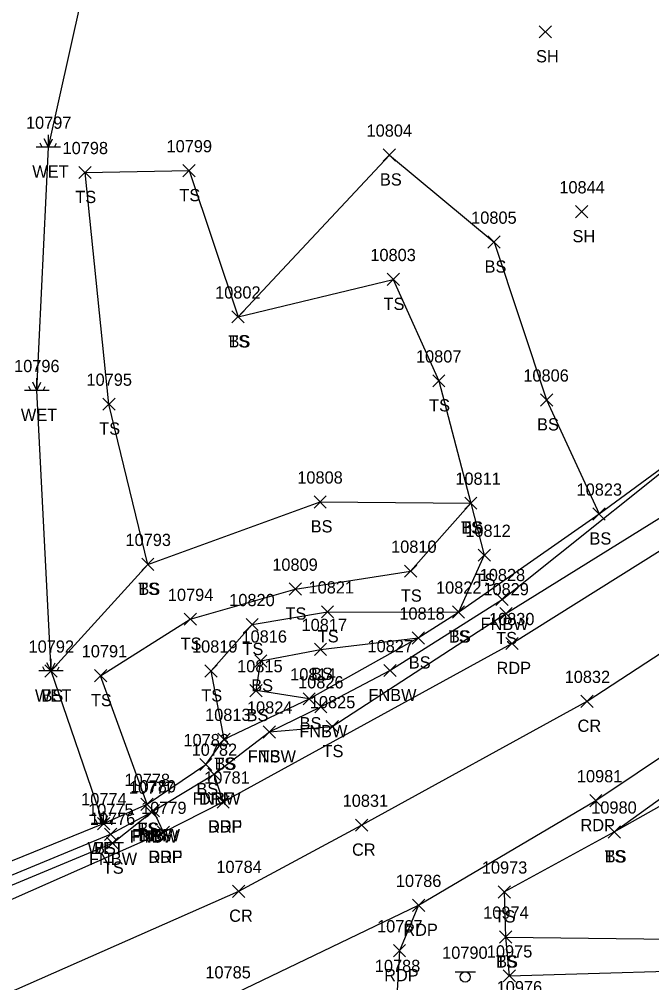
# Model space of a CAD drawing. Extents: x 1475671 to 1477951, y 592661 to 593821.
# Drawn here: x 1476484.8 to 1476588.2, y 593075.6 to 593233.2 of the extents above; entities that cross this region are included whole.
import ezdxf

# ---------------------------------------------------------------- set-up
doc = ezdxf.new("R2010")
doc.units = 0
for name, color, linetype in [('L_A', 7, 'Continuous'), ('L_I', 7, 'Continuous'), ('L_TIC', 7, 'Continuous'), ('LELB', 7, 'Continuous'), ('LFNC', 7, 'Continuous'), ('LWET', 7, 'Continuous'), ('P_A', 7, 'Continuous'), ('P_I', 7, 'Continuous'), ('P_TIC', 7, 'Continuous'), ('PET', 7, 'Continuous'), ('PRC', 7, 'Continuous'), ('R_A', 7, 'Continuous'), ('R_I', 7, 'Continuous'), ('R_TIC', 7, 'Continuous'), ('RDF', 7, 'Continuous'), ('S_I', 7, 'Continuous'), ('SSGN', 7, 'Continuous')]:
    doc.layers.add(name, color=color, linetype=linetype)

msp = doc.modelspace()

# ---------------------------------------------------------------- linework, layer by layer
at = {"layer": 'L_TIC'}
for points in [[(1476569.83, 593230.17), (1476571.83, 593232.17)], [(1476571.83, 593230.17), (1476569.83, 593232.17)], [(1476544.34, 593210.01), (1476546.34, 593212.01)], [(1476546.34, 593210.01), (1476544.34, 593212.01)], [(1476494.55, 593207.15), (1476496.55, 593209.15)], [(1476496.55, 593207.15), (1476494.55, 593209.15)], [(1476511.57, 593207.45), (1476513.57, 593209.45)], [(1476513.57, 593207.45), (1476511.57, 593209.45)], [(1476575.79, 593200.73), (1476577.79, 593202.73)], [(1476577.79, 593200.73), (1476575.79, 593202.73)], [(1476561.46, 593195.76), (1476563.46, 593197.76)], [(1476563.46, 593195.76), (1476561.46, 593197.76)], [(1476544.97, 593189.65), (1476546.97, 593191.65)], [(1476546.97, 593189.65), (1476544.97, 593191.65)], [(1476519.58, 593183.52), (1476521.58, 593185.52)], [(1476521.58, 593183.52), (1476519.58, 593185.52)], [(1476519.58, 593183.52), (1476521.58, 593185.52)], [(1476521.58, 593183.52), (1476519.58, 593185.52)], [(1476552.42, 593173.05), (1476554.42, 593175.05)], [(1476554.42, 593173.05), (1476552.42, 593175.05)], [(1476498.46, 593169.24), (1476500.46, 593171.24)], [(1476500.46, 593169.24), (1476498.46, 593171.24)], [(1476570.05, 593169.93), (1476572.05, 593171.93)], [(1476572.05, 593169.93), (1476570.05, 593171.93)], [(1476533.02, 593153.24), (1476535.02, 593155.24)], [(1476535.02, 593153.24), (1476533.02, 593155.24)], [(1476557.65, 593153.04), (1476559.65, 593155.04)], [(1476559.65, 593153.04), (1476557.65, 593155.04)], [(1476557.65, 593153.04), (1476559.65, 593155.04)], [(1476559.65, 593153.04), (1476557.65, 593155.04)], [(1476557.65, 593153.04), (1476559.65, 593155.04)], [(1476559.65, 593153.04), (1476557.65, 593155.04)], [(1476578.62, 593151.26), (1476580.62, 593153.26)], [(1476580.62, 593151.26), (1476578.62, 593153.26)], [(1476578.62, 593151.26), (1476580.62, 593153.26)], [(1476580.62, 593151.26), (1476578.62, 593153.26)], [(1476559.85, 593144.52), (1476561.85, 593146.52)], [(1476561.85, 593144.52), (1476559.85, 593146.52)], [(1476504.83, 593143.02), (1476506.83, 593145.02)], [(1476506.83, 593143.02), (1476504.83, 593145.02)], [(1476504.83, 593143.02), (1476506.83, 593145.02)], [(1476506.83, 593143.02), (1476504.83, 593145.02)], [(1476547.8, 593141.91), (1476549.8, 593143.91)], [(1476549.8, 593141.91), (1476547.8, 593143.91)], [(1476528.94, 593138.97), (1476530.94, 593140.97)], [(1476530.94, 593138.97), (1476528.94, 593140.97)], [(1476562.76, 593137.28), (1476564.76, 593139.28)], [(1476564.76, 593137.28), (1476562.76, 593139.28)], [(1476511.77, 593134.04), (1476513.77, 593136.04)], [(1476513.77, 593134.04), (1476511.77, 593136.04)], [(1476534.22, 593135.25), (1476536.22, 593137.25)], [(1476536.22, 593135.25), (1476534.22, 593137.25)], [(1476555.63, 593135.22), (1476557.63, 593137.22)], [(1476557.63, 593135.22), (1476555.63, 593137.22)], [(1476555.63, 593135.22), (1476557.63, 593137.22)], [(1476557.63, 593135.22), (1476555.63, 593137.22)], [(1476555.63, 593135.22), (1476557.63, 593137.22)], [(1476557.63, 593135.22), (1476555.63, 593137.22)], [(1476563.39, 593134.96), (1476565.39, 593136.96)], [(1476565.39, 593134.96), (1476563.39, 593136.96)], [(1476521.89, 593133.18), (1476523.89, 593135.18)], [(1476523.89, 593133.18), (1476521.89, 593135.18)], [(1476549.06, 593130.97), (1476551.06, 593132.97)], [(1476551.06, 593130.97), (1476549.06, 593132.97)], [(1476549.06, 593130.97), (1476551.06, 593132.97)], [(1476551.06, 593130.97), (1476549.06, 593132.97)], [(1476533.07, 593129.11), (1476535.07, 593131.11)], [(1476535.07, 593129.11), (1476533.07, 593131.11)], [(1476523.3, 593127.22), (1476525.3, 593129.22)], [(1476525.3, 593127.22), (1476523.3, 593129.22)], [(1476488.99, 593125.57), (1476490.99, 593127.57)], [(1476490.99, 593125.57), (1476488.99, 593127.57)], [(1476497.11, 593124.8), (1476499.11, 593126.8)], [(1476499.11, 593124.8), (1476497.11, 593126.8)], [(1476515.16, 593125.58), (1476517.16, 593127.58)], [(1476517.16, 593125.58), (1476515.16, 593127.58)], [(1476544.43, 593125.64), (1476546.43, 593127.64)], [(1476546.43, 593125.64), (1476544.43, 593127.64)], [(1476522.53, 593122.35), (1476524.53, 593124.35)], [(1476524.53, 593122.35), (1476522.53, 593124.35)], [(1476531.21, 593121.02), (1476533.21, 593123.02)], [(1476533.21, 593121.02), (1476531.21, 593123.02)], [(1476531.21, 593121.02), (1476533.21, 593123.02)], [(1476533.21, 593121.02), (1476531.21, 593123.02)], [(1476533.13, 593119.72), (1476535.13, 593121.72)], [(1476535.13, 593119.72), (1476533.13, 593121.72)], [(1476524.71, 593115.6), (1476526.71, 593117.6)], [(1476526.71, 593115.6), (1476524.71, 593117.6)], [(1476524.71, 593115.6), (1476526.71, 593117.6)], [(1476526.71, 593115.6), (1476524.71, 593117.6)], [(1476534.99, 593116.47), (1476536.99, 593118.47)], [(1476536.99, 593116.47), (1476534.99, 593118.47)], [(1476517.29, 593114.4), (1476519.29, 593116.4)], [(1476519.29, 593114.4), (1476517.29, 593116.4)], [(1476517.29, 593114.4), (1476519.29, 593116.4)], [(1476519.29, 593114.4), (1476517.29, 593116.4)], [(1476514.32, 593110.26), (1476516.32, 593112.26)], [(1476516.32, 593110.26), (1476514.32, 593112.26)], [(1476515.66, 593108.69), (1476517.66, 593110.69)], [(1476517.66, 593108.69), (1476515.66, 593110.69)], [(1476504.69, 593103.75), (1476506.69, 593105.75)], [(1476506.69, 593103.75), (1476504.69, 593105.75)], [(1476504.69, 593103.75), (1476506.69, 593105.75)], [(1476506.69, 593103.75), (1476504.69, 593105.75)], [(1476505.4, 593102.47), (1476507.4, 593104.47)], [(1476507.4, 593102.47), (1476505.4, 593104.47)], [(1476505.4, 593102.47), (1476507.4, 593104.47)], [(1476507.4, 593102.47), (1476505.4, 593104.47)], [(1476505.74, 593102.7), (1476507.74, 593104.7)], [(1476507.74, 593102.7), (1476505.74, 593104.7)], [(1476497.59, 593100.6), (1476499.59, 593102.6)], [(1476499.59, 593100.6), (1476497.59, 593102.6)], [(1476581.11, 593099.23), (1476583.11, 593101.23)], [(1476583.11, 593099.23), (1476581.11, 593101.23)], [(1476581.11, 593099.23), (1476583.11, 593101.23)], [(1476583.11, 593099.23), (1476581.11, 593101.23)], [(1476498.73, 593098.84), (1476500.73, 593100.84)], [(1476500.73, 593098.84), (1476498.73, 593100.84)], [(1476499.05, 593097.39), (1476501.05, 593099.39)], [(1476501.05, 593097.39), (1476499.05, 593099.39)], [(1476563.12, 593089.41), (1476565.12, 593091.41)], [(1476565.12, 593089.41), (1476563.12, 593091.41)], [(1476563.12, 593089.41), (1476565.12, 593091.41)], [(1476565.12, 593089.41), (1476563.12, 593091.41)], [(1476563.35, 593082.03), (1476565.35, 593084.03)], [(1476565.35, 593082.03), (1476563.35, 593084.03)], [(1476563.35, 593082.03), (1476565.35, 593084.03)], [(1476565.35, 593082.03), (1476563.35, 593084.03)], [(1476563.94, 593075.68), (1476565.94, 593077.68)], [(1476565.94, 593075.68), (1476563.94, 593077.68)]]:
    msp.add_lwpolyline(points, dxfattribs=at)
at = {"layer": 'LELB'}
for points in [[(1476525.71, 593116.6), (1476535.99, 593117.47), (1476564.39, 593135.96), (1476604.97, 593161.16), (1476624.83, 593173.86), (1476638.09, 593183.34), (1476660.79, 593199.46), (1476676.81, 593212.32), (1476707.13, 593238.69), (1476723.81, 593252.6), (1476754.14, 593278.44), (1476785.31, 593303.01), (1476812.8, 593326.19), (1476842.99, 593352.59), (1476863.07, 593369.43), (1476886.56, 593389.77), (1476893.66, 593396.85), (1476901.2, 593401.68), (1476921.17, 593422.2)], [(1476564.12, 593090.41), (1476582.11, 593100.23), (1476611.48, 593121.39), (1476618.84, 593125.52), (1476623.35, 593128.86), (1476625.72, 593132.79), (1476629.36, 593135.67), (1476655.41, 593152.72), (1476679.21, 593171.49), (1476707, 593193.97), (1476724.55, 593208.7), (1476750.98, 593231.69), (1476770.54, 593248.26), (1476798.66, 593272.17), (1476825.82, 593296.2), (1476846.6, 593313.13), (1476851.35, 593312.9), (1476856.13, 593310.72)], [(1476520.58, 593184.52), (1476545.34, 593211.01), (1476562.46, 593196.76), (1476571.05, 593170.93), (1476579.62, 593152.26)], [(1476505.83, 593144.02), (1476499.46, 593170.24), (1476495.55, 593208.15), (1476512.57, 593208.45), (1476520.58, 593184.52), (1476545.97, 593190.65), (1476553.42, 593174.05), (1476558.65, 593154.04)], [(1476498.59, 593101.6), (1476505.69, 593104.75), (1476515.32, 593111.26), (1476518.29, 593115.4), (1476532.21, 593122.02), (1476550.06, 593131.97), (1476556.63, 593136.22), (1476579.62, 593152.26), (1476600.34, 593167.51), (1476602.47, 593173.82), (1476609.32, 593177.24)], [(1476489.99, 593126.57), (1476505.83, 593144.02), (1476534.02, 593154.24), (1476558.65, 593154.04)], [(1476505.69, 593104.75), (1476498.11, 593125.8), (1476512.77, 593135.04), (1476529.94, 593139.97), (1476548.8, 593142.91), (1476558.65, 593154.04), (1476560.85, 593145.52), (1476556.63, 593136.22)], [(1476518.29, 593115.4), (1476516.16, 593126.58), (1476522.89, 593134.18), (1476535.22, 593136.25), (1476556.63, 593136.22)], [(1476532.21, 593122.02), (1476523.53, 593123.35), (1476524.3, 593128.22), (1476534.07, 593130.11), (1476550.06, 593131.97)], [(1476582.11, 593100.23), (1476614.41, 593118.48), (1476620.24, 593123.64)], [(1476399.83, 593064.01), (1476416.3, 593067.79), (1476459.07, 593081.3), (1476500.05, 593098.39), (1476506.4, 593103.47)], [(1476564.12, 593090.41), (1476564.35, 593083.03), (1476564.94, 593076.68), (1476605.53, 593077.89), (1476635.38, 593080.86), (1476648.64, 593080.65), (1476656.7, 593082.36), (1476660.67, 593090.95), (1476671.66, 593086.36), (1476683.75, 593088.18), (1476716.34, 593096.61), (1476747.99, 593101.23)], [(1476564.35, 593083.03), (1476605.05, 593082.49), (1476634.15, 593084.51)]]:
    msp.add_lwpolyline(points, dxfattribs=at)
at = {"layer": 'LFNC'}
msp.add_lwpolyline([(1476458.99, 593083.01), (1476499.73, 593099.84), (1476506.4, 593103.47), (1476506.74, 593103.7), (1476516.66, 593109.69), (1476525.71, 593116.6), (1476534.13, 593120.72), (1476545.43, 593126.64), (1476563.76, 593138.28), (1476600.34, 593167.51), (1476610.45, 593174.4), (1476612.65, 593176.23), (1476618.95, 593180.66), (1476640, 593195.61), (1476653.4, 593207.77), (1476664.49, 593217.17), (1476691.69, 593239.4), (1476702.63, 593247.23), (1476709.5, 593251.9), (1476716.55, 593257.09), (1476733.12, 593270.47), (1476759.81, 593293.37)], dxfattribs=at)
at = {"layer": 'LWET'}
for p, q in [((1476489.56, 593212.3), (1476488.89, 593213.63)), ((1476489.56, 593212.3), (1476489.56, 593214.3)), ((1476489.56, 593212.3), (1476490.22, 593213.63)), ((1476491.56, 593212.3), (1476487.56, 593212.3)), ((1476488.56, 593212.3), (1476488.22, 593212.97)), ((1476490.56, 593212.3), (1476490.89, 593212.97)), ((1476487.68, 593172.48), (1476487.01, 593173.81)), ((1476487.68, 593172.48), (1476487.68, 593174.48)), ((1476487.68, 593172.48), (1476488.34, 593173.81)), ((1476489.68, 593172.48), (1476485.68, 593172.48)), ((1476486.68, 593172.48), (1476486.34, 593173.15)), ((1476488.68, 593172.48), (1476489.01, 593173.15)), ((1476489.99, 593126.57), (1476489.99, 593128.57)), ((1476491.99, 593126.57), (1476487.99, 593126.57)), ((1476488.99, 593126.57), (1476488.66, 593127.24)), ((1476489.99, 593126.57), (1476489.33, 593127.9)), ((1476489.99, 593126.57), (1476490.66, 593127.9)), ((1476490.99, 593126.57), (1476491.33, 593127.24)), ((1476498.59, 593101.6), (1476497.93, 593102.93)), ((1476498.59, 593101.6), (1476498.59, 593103.6)), ((1476498.59, 593101.6), (1476499.26, 593102.93)), ((1476500.59, 593101.6), (1476496.59, 593101.6)), ((1476497.59, 593101.6), (1476497.26, 593102.26)), ((1476499.59, 593101.6), (1476499.93, 593102.26))]:
    msp.add_line(p, q, dxfattribs=at)
msp.add_lwpolyline([(1476438.09, 593181.37), (1476442.92, 593155.18), (1476449.77, 593118.79), (1476457.34, 593084.84), (1476498.59, 593101.6), (1476489.99, 593126.57), (1476487.68, 593172.48), (1476489.56, 593212.3), (1476496.66, 593244.14)], dxfattribs=at)
at = {"layer": 'P_TIC'}
for points in [[(1476564.38, 593130.07), (1476566.38, 593132.07)], [(1476566.38, 593130.07), (1476564.38, 593132.07)], [(1476576.67, 593120.61), (1476578.67, 593122.61)], [(1476578.67, 593120.61), (1476576.67, 593122.61)], [(1476517.15, 593104.13), (1476519.15, 593106.13)], [(1476519.15, 593104.13), (1476517.15, 593106.13)], [(1476578.1, 593104.35), (1476580.1, 593106.35)], [(1476580.1, 593104.35), (1476578.1, 593106.35)], [(1476539.79, 593100.34), (1476541.79, 593102.34)], [(1476541.79, 593100.34), (1476539.79, 593102.34)], [(1476507.39, 593099.17), (1476509.39, 593101.17)], [(1476509.39, 593099.17), (1476507.39, 593101.17)], [(1476519.7, 593089.52), (1476521.7, 593091.52)], [(1476521.7, 593089.52), (1476519.7, 593091.52)], [(1476549.12, 593087.22), (1476551.12, 593089.22)], [(1476551.12, 593087.22), (1476549.12, 593089.22)], [(1476549.12, 593087.22), (1476551.12, 593089.22)], [(1476551.12, 593087.22), (1476549.12, 593089.22)], [(1476545.99, 593079.79), (1476547.99, 593081.79)], [(1476547.99, 593079.79), (1476545.99, 593081.79)]]:
    msp.add_lwpolyline(points, dxfattribs=at)
at = {"layer": 'PET'}
for points in [[(1476459.25, 593078.48), (1476508.39, 593100.17), (1476518.15, 593105.13), (1476565.38, 593131.07), (1476607.43, 593157.45), (1476640.25, 593180.54), (1476678.21, 593210.57), (1476708.64, 593235.75), (1476725.67, 593249.83), (1476755.84, 593275.3), (1476786.3, 593300.73), (1476814.32, 593324.28), (1476845.05, 593350.02), (1476865.02, 593366.82), (1476897.04, 593395.14), (1476922.98, 593419.08), (1476952.36, 593443.37)], [(1476493.61, 593061.9), (1476518.9, 593073.26), (1476550.12, 593088.22), (1476579.1, 593105.35), (1476612.57, 593127.79), (1476627.64, 593138.01), (1476653.65, 593155.86), (1476677.37, 593174.62), (1476705.43, 593196.67), (1476722.66, 593210.69), (1476749.61, 593233.45), (1476768.81, 593249.96), (1476797.5, 593274.02), (1476824.82, 593297.55), (1476845, 593315.29), (1476868.19, 593333.86), (1476888.66, 593352.98), (1476918.01, 593376.95), (1476944.23, 593398.87), (1476967.73, 593418.7), (1476998.53, 593444.47)], [(1476550.12, 593088.22), (1476546.99, 593080.79), (1476546.62, 593074.3), (1476558.02, 593070.45), (1476566.6, 593070.83), (1476605.7, 593074.02), (1476651.65, 593078.89), (1476683.81, 593086.28), (1476716.78, 593091.72), (1476756.3, 593096.32), (1476786.76, 593094.61), (1476795.52, 593092.66), (1476816.88, 593085.29), (1476835.43, 593074.22), (1476828.62, 593102.02), (1476824.42, 593119.75), (1476821.59, 593140.77), (1476821.02, 593163.56), (1476821.92, 593180.44), (1476827.12, 593207.84), (1476837.47, 593243.39), (1476848.83, 593278.3), (1476858.44, 593303.19), (1476868.19, 593333.86)]]:
    msp.add_lwpolyline(points, dxfattribs=at)
at = {"layer": 'PRC'}
msp.add_lwpolyline([(1476461.98, 593064.62), (1476520.7, 593090.52), (1476540.79, 593101.34), (1476577.67, 593121.61), (1476614.51, 593145.69), (1476649.36, 593170.81), (1476687.02, 593200.01), (1476716.69, 593224.25), (1476733.58, 593238.31), (1476760.9, 593261.21), (1476795.35, 593290.14), (1476823.06, 593313.51), (1476854.07, 593339.52), (1476875.7, 593357.51), (1476907.01, 593384.08), (1476934.06, 593407.68), (1476963.46, 593432.81)], dxfattribs=at)
at = {"layer": 'R_TIC'}
for points in [[(1476515.66, 593108.69), (1476517.66, 593110.69)], [(1476517.66, 593108.69), (1476515.66, 593110.69)], [(1476517.15, 593104.13), (1476519.15, 593106.13)], [(1476519.15, 593104.13), (1476517.15, 593106.13)], [(1476505.74, 593102.7), (1476507.74, 593104.7)], [(1476507.74, 593102.7), (1476505.74, 593104.7)], [(1476507.39, 593099.17), (1476509.39, 593101.17)], [(1476509.39, 593099.17), (1476507.39, 593101.17)]]:
    msp.add_lwpolyline(points, dxfattribs=at)
at = {"layer": 'RDF'}
for points in [[(1476518.15, 593105.13), (1476516.66, 593109.69)], [(1476508.39, 593100.17), (1476506.74, 593103.7)]]:
    msp.add_lwpolyline(points, dxfattribs=at)
at = {"layer": 'SSGN'}
for p, q in [((1476556.09, 593077.32), (1476559.42, 593077.32)), ((1476557.74, 593076.49), (1476557.74, 593076.49))]:
    msp.add_line(p, q, dxfattribs=at)
msp.add_circle((1476557.74, 593076.49), 0.833, dxfattribs=at)

# ---------------------------------------------------------------- texts
at = {"layer": 'L_A'}
for s, p in [('SH', (1476569.32, 593226.17)), ('WET', (1476486.93, 593207.3)), ('BS', (1476543.79, 593206.01)), ('TS', (1476510.98, 593203.45)), ('TS', (1476493.96, 593203.15)), ('SH', (1476575.28, 593196.73)), ('BS', (1476560.9, 593191.76)), ('TS', (1476544.38, 593185.65)), ('TS', (1476518.99, 593179.52)), ('BS', (1476519.02, 593179.52)), ('TS', (1476551.83, 593169.05)), ('WET', (1476485.06, 593167.48)), ('BS', (1476569.49, 593165.93)), ('TS', (1476497.87, 593165.24)), ('BS', (1476532.46, 593149.24)), ('TS', (1476557.06, 593149.04)), ('TS', (1476557.06, 593149.04)), ('BS', (1476557.1, 593149.04)), ('BS', (1476578.06, 593147.26)), ('BS', (1476578.06, 593147.26)), ('TS', (1476559.26, 593140.52)), ('TS', (1476504.24, 593139.02)), ('BS', (1476504.28, 593139.02)), ('TS', (1476547.21, 593137.91)), ('TS', (1476528.34, 593134.97)), ('FNBW', (1476560.24, 593133.28)), ('TS', (1476533.62, 593131.25)), ('TS', (1476555.04, 593131.22)), ('TS', (1476555.04, 593131.22)), ('BS', (1476555.07, 593131.22)), ('TS', (1476562.8, 593130.96)), ('TS', (1476511.18, 593130.04)), ('TS', (1476521.3, 593129.18)), ('BS', (1476548.51, 593126.97)), ('BS', (1476548.51, 593126.97)), ('BS', (1476532.51, 593125.11)), ('BS', (1476522.74, 593123.22)), ('WET', (1476487.37, 593121.57)), ('BS', (1476488.43, 593121.57)), ('TS', (1476514.57, 593121.58)), ('FNBW', (1476541.9, 593121.64)), ('TS', (1476496.52, 593120.8)), ('BS', (1476521.97, 593118.35)), ('BS', (1476530.65, 593117.02)), ('BS', (1476530.65, 593117.02)), ('FNBW', (1476530.6, 593115.72)), ('TS', (1476534.4, 593112.47)), ('TS', (1476516.7, 593110.4)), ('BS', (1476516.73, 593110.4)), ('FNBW', (1476522.18, 593111.6)), ('TS', (1476524.12, 593111.6)), ('BS', (1476513.76, 593106.26)), ('FNBW', (1476513.13, 593104.69)), ('TS', (1476504.1, 593099.75)), ('BS', (1476504.13, 593099.75)), ('FNBW', (1476502.87, 593098.47)), ('FNBW', (1476503.21, 593098.7)), ('TS', (1476504.81, 593098.47)), ('WET', (1476495.97, 593096.6)), ('BS', (1476497.03, 593096.6)), ('FNBW', (1476496.2, 593094.84)), ('TS', (1476580.52, 593095.23)), ('BS', (1476580.55, 593095.23)), ('TS', (1476498.46, 593093.39)), ('TS', (1476562.53, 593085.41)), ('TS', (1476562.53, 593085.41)), ('TS', (1476562.76, 593078.03)), ('BS', (1476562.79, 593078.03))]:
    msp.add_text(s, height=2, dxfattribs=at).set_placement(p)
at = {"layer": 'L_I'}
for s, p in [('10797', (1476485.89, 593215.3)), ('10804', (1476541.6, 593214.01)), ('10798', (1476491.88, 593211.15)), ('10799', (1476508.89, 593211.45)), ('10844', (1476573.13, 593204.73)), ('10805', (1476558.71, 593199.76)), ('10803', (1476542.22, 593193.65)), ('10802', (1476516.83, 593187.52)), ('10802', (1476516.83, 593187.52)), ('10807', (1476549.68, 593177.05)), ('10796', (1476483.95, 593175.48)), ('10806', (1476567.24, 593173.93)), ('10795', (1476495.79, 593173.24)), ('10808', (1476530.27, 593157.24)), ('10811', (1476556.12, 593157.04)), ('10811', (1476556.12, 593157.04)), ('10811', (1476556.12, 593157.04)), ('10823', (1476575.95, 593155.26)), ('10823', (1476575.95, 593155.26)), ('10812', (1476557.75, 593148.52)), ('10793', (1476502.17, 593147.02)), ('10793', (1476502.17, 593147.02)), ('10810', (1476545.61, 593145.91)), ('10809', (1476526.18, 593142.97)), ('10828', (1476560.1, 593141.28)), ('10821', (1476532.11, 593139.25)), ('10822', (1476552.96, 593139.22)), ('10822', (1476552.96, 593139.22)), ('10822', (1476552.96, 593139.22)), ('10829', (1476560.71, 593138.96)), ('10794', (1476509.1, 593138.04)), ('10820', (1476519.14, 593137.18)), ('10818', (1476546.96, 593134.97)), ('10818', (1476546.96, 593134.97)), ('10817', (1476530.97, 593133.11)), ('10816', (1476521.14, 593131.22)), ('10792', (1476486.32, 593129.57)), ('10792', (1476486.32, 593129.57)), ('10819', (1476513.05, 593129.58)), ('10827', (1476541.76, 593129.64)), ('10791', (1476495.01, 593128.8)), ('10815', (1476520.43, 593126.35)), ('10814', (1476529.11, 593125.02)), ('10814', (1476529.11, 593125.02)), ('10826', (1476530.4, 593123.72)), ('10825', (1476532.32, 593120.47)), ('10813', (1476515.19, 593118.4)), ('10813', (1476515.19, 593118.4)), ('10824', (1476522.04, 593119.6)), ('10824', (1476522.04, 593119.6)), ('10783', (1476511.65, 593114.26)), ('10782', (1476512.99, 593112.69)), ('10778', (1476502.02, 593107.75)), ('10778', (1476502.02, 593107.75)), ('10777', (1476502.73, 593106.47)), ('10777', (1476502.73, 593106.47)), ('10780', (1476502.99, 593106.7)), ('10774', (1476494.92, 593104.6)), ('10774', (1476494.92, 593104.6)), ('10775', (1476496.06, 593102.84)), ('10980', (1476578.35, 593103.23)), ('10980', (1476578.35, 593103.23)), ('10776', (1476496.33, 593101.39)), ('10973', (1476560.45, 593093.41)), ('10973', (1476560.45, 593093.41)), ('10974', (1476560.68, 593086.03)), ('10974', (1476560.68, 593086.03)), ('10975', (1476561.27, 593079.68))]:
    msp.add_text(s, height=2, dxfattribs=at).set_placement(p)
at = {"layer": 'P_A'}
for s, p in [('RDP', (1476562.86, 593126.07)), ('CR', (1476576.11, 593116.61)), ('RDP', (1476515.64, 593100.13)), ('RDP', (1476576.59, 593100.35)), ('CR', (1476539.22, 593096.34)), ('RDP', (1476505.88, 593095.17)), ('CR', (1476519.13, 593085.52)), ('RDP', (1476547.61, 593083.22)), ('RDP', (1476547.61, 593083.22)), ('RDP', (1476544.48, 593075.79))]:
    msp.add_text(s, height=2, dxfattribs=at).set_placement(p)
at = {"layer": 'P_I'}
for s, p in [('10830', (1476561.62, 593134.07)), ('10832', (1476574, 593124.61)), ('10781', (1476515.05, 593108.13)), ('10981', (1476576, 593108.35)), ('10831', (1476537.69, 593104.34)), ('10779', (1476504.72, 593103.17)), ('10784', (1476517.03, 593093.52)), ('10786', (1476546.4, 593091.22)), ('10786', (1476546.4, 593091.22)), ('10787', (1476543.32, 593083.79)), ('10788', (1476542.95, 593077.3)), ('10785', (1476515.23, 593076.26)), ('10976', (1476562.88, 593073.83))]:
    msp.add_text(s, height=2, dxfattribs=at).set_placement(p)
at = {"layer": 'R_A'}
for p in [(1476514.2, 593104.69), (1476515.68, 593100.13), (1476504.28, 593098.7), (1476505.93, 593095.17)]:
    msp.add_text('DRF', height=2, dxfattribs=at).set_placement(p)
at = {"layer": 'R_I'}
for s, p in [('10782', (1476512.99, 593112.69)), ('10781', (1476515.05, 593108.13)), ('10780', (1476502.99, 593106.7)), ('10779', (1476504.72, 593103.17))]:
    msp.add_text(s, height=2, dxfattribs=at).set_placement(p)
at = {"layer": 'S_I'}
msp.add_text('10790', height=2, dxfattribs=at).set_placement((1476553.96, 593079.47))

doc.saveas('drawing.dxf')
